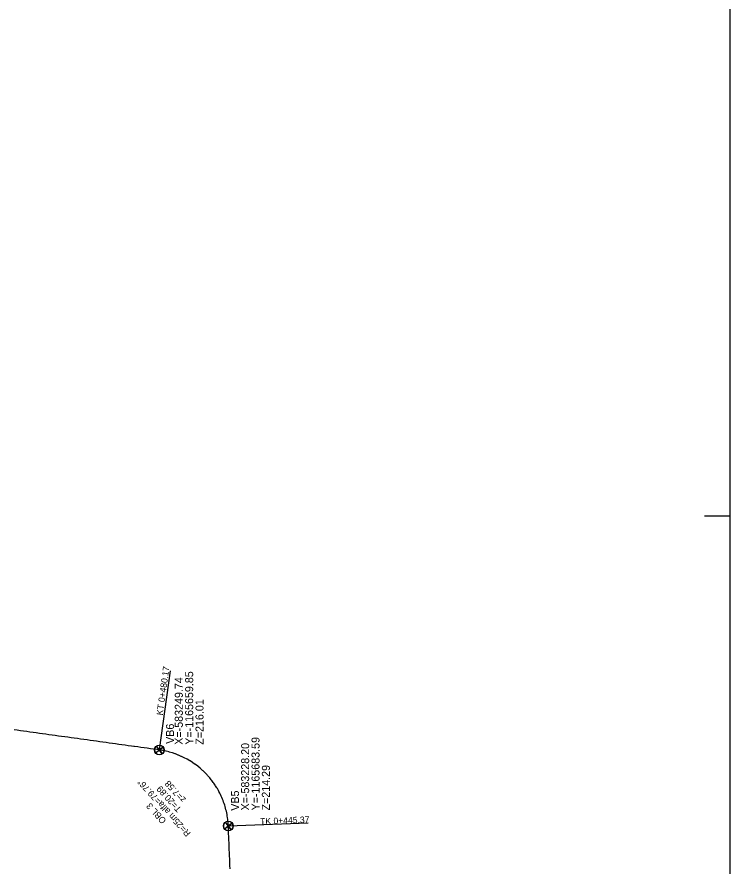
# Model space of a CAD drawing. Extents: x -583517 to -548566, y -1166112 to -1101582.
# Drawn here: x -583294.2 to -583071.5, y -1165696.4 to -1165430.8 of the extents above; entities that cross this region are included whole.
import ezdxf

# ---------------------------------------------------------------- set-up
doc = ezdxf.new("R2010")
doc.units = 0
for name, color, linetype in [('13', 7, 'Continuous'), ('59', 7, 'Continuous'), ('8', 7, 'Continuous'), ('Body pricny rez', 7, 'Continuous'), ('Popis pricneho profilu', 7, 'Continuous')]:
    doc.layers.add(name, color=color, linetype=linetype)

msp = doc.modelspace()

# ---------------------------------------------------------------- linework, layer by layer
at = {"layer": '13'}
for points in [[(-583249.74, -1165659.85), (-583246.31, -1165635.09)], [(-583228.2, -1165683.59), (-583203.22, -1165682.57)]]:
    msp.add_lwpolyline(points, dxfattribs=at)
at = {"layer": '8'}
for p, q in [((-583250.95, -1165660.74), (-583248.54, -1165658.95)), ((-583250.95, -1165660.74), (-583249.74, -1165659.85)), ((-583249.74, -1165659.85), (-583250.64, -1165658.64)), ((-583248.85, -1165661.05), (-583250.64, -1165658.65)), ((-583248.54, -1165658.95), (-583249.74, -1165659.85)), ((-583248.54, -1165658.95), (-583249.74, -1165659.85)), ((-583249.74, -1165659.85), (-583248.85, -1165661.05)), ((-583249.74, -1165659.85), (-583248.85, -1165661.05)), ((-583227.3, -1165684.79), (-583229.09, -1165682.39)), ((-583228.2, -1165683.59), (-583229.09, -1165682.39)), ((-583229.4, -1165684.48), (-583226.99, -1165682.69)), ((-583229.4, -1165684.48), (-583228.2, -1165683.59)), ((-583226.99, -1165682.69), (-583228.2, -1165683.59)), ((-583226.99, -1165682.69), (-583228.2, -1165683.59)), ((-583228.2, -1165683.59), (-583227.3, -1165684.79)), ((-583228.2, -1165683.59), (-583227.3, -1165684.79))]:
    msp.add_line(p, q, dxfattribs=at)
for centre in [(-583249.74, -1165659.85), (-583228.2, -1165683.59)]:
    msp.add_circle(centre, 1.5, dxfattribs=at)
for centre, start, end in [((-583249.74, -1165659.85), 126.6271, 216.6271), ((-583249.74, -1165659.85), 306.6271, 36.6271), ((-583249.74, -1165659.85), 306.6271, 36.6271), ((-583228.2, -1165683.59), 126.6271, 216.6271), ((-583228.2, -1165683.59), 306.6271, 36.6271), ((-583228.2, -1165683.59), 306.6271, 36.6271)]:
    msp.add_arc(centre, 1.5, start, end, dxfattribs=at)
at = {"layer": 'Body pricny rez'}
msp.add_lwpolyline([(-583227.65, -1165696.95), (-583227.69, -1165695.95), (-583227.73, -1165694.95), (-583227.77, -1165693.95), (-583227.81, -1165692.95), (-583227.85, -1165691.95), (-583227.9, -1165690.96), (-583227.91, -1165690.71), (-583227.94, -1165689.96), (-583227.98, -1165688.96), (-583228.02, -1165687.96), (-583228.06, -1165686.96), (-583228.1, -1165685.96), (-583228.14, -1165684.96), (-583228.18, -1165683.96), (-583228.2, -1165683.59), (-583228.23, -1165682.96), (-583228.26, -1165682.57), (-583228.32, -1165681.97), (-583228.36, -1165681.55), (-583228.44, -1165680.97), (-583228.51, -1165680.54), (-583228.61, -1165679.99), (-583228.7, -1165679.53), (-583228.81, -1165679.01), (-583228.93, -1165678.53), (-583229.06, -1165678.04), (-583229.2, -1165677.55), (-583229.34, -1165677.08), (-583229.5, -1165676.57), (-583229.66, -1165676.13), (-583229.85, -1165675.61), (-583230.02, -1165675.2), (-583230.24, -1165674.66), (-583230.41, -1165674.28), (-583230.67, -1165673.73), (-583230.84, -1165673.38), (-583231.13, -1165672.82), (-583231.31, -1165672.49), (-583231.63, -1165671.93), (-583231.81, -1165671.63), (-583232.17, -1165671.05), (-583232.35, -1165670.79), (-583232.74, -1165670.21), (-583232.92, -1165669.96), (-583233.35, -1165669.38), (-583233.52, -1165669.17), (-583233.99, -1165668.58), (-583234.15, -1165668.39), (-583234.66, -1165667.81), (-583234.82, -1165667.64), (-583235.37, -1165667.07), (-583235.51, -1165666.92), (-583236.1, -1165666.35), (-583236.23, -1165666.23), (-583236.86, -1165665.67), (-583236.98, -1165665.57), (-583237.65, -1165665.02), (-583237.75, -1165664.94), (-583238.47, -1165664.4), (-583238.55, -1165664.33), (-583239.3, -1165663.81), (-583239.38, -1165663.77), (-583240.17, -1165663.26), (-583240.22, -1165663.23), (-583241.05, -1165662.75), (-583241.09, -1165662.73), (-583241.96, -1165662.27), (-583241.97, -1165662.26), (-583242.87, -1165661.83), (-583242.88, -1165661.83), (-583243.79, -1165661.44), (-583243.82, -1165661.43), (-583244.73, -1165661.08), (-583244.78, -1165661.06), (-583245.67, -1165660.76), (-583245.75, -1165660.74), (-583246.63, -1165660.48), (-583246.73, -1165660.46), (-583247.6, -1165660.24), (-583247.73, -1165660.21), (-583248.58, -1165660.04), (-583248.73, -1165660.01), (-583249.57, -1165659.87), (-583249.74, -1165659.85), (-583250.56, -1165659.74), (-583251.55, -1165659.6), (-583252.54, -1165659.46), (-583253.53, -1165659.32), (-583254.52, -1165659.19), (-583255.51, -1165659.05), (-583256.5, -1165658.91), (-583257.49, -1165658.77), (-583257.74, -1165658.74), (-583258.48, -1165658.64), (-583259.47, -1165658.5), (-583260.46, -1165658.36), (-583261.46, -1165658.22), (-583262.45, -1165658.09), (-583263.44, -1165657.95), (-583264.43, -1165657.81), (-583265.42, -1165657.68), (-583266.41, -1165657.54), (-583267.4, -1165657.4), (-583268.39, -1165657.26), (-583269.38, -1165657.13), (-583270.37, -1165656.99), (-583271.36, -1165656.85), (-583272.35, -1165656.71), (-583273.34, -1165656.58), (-583274.33, -1165656.44), (-583275.32, -1165656.3), (-583276.31, -1165656.16), (-583277.3, -1165656.03), (-583278.29, -1165655.89), (-583279.28, -1165655.75), (-583280.28, -1165655.62), (-583281.27, -1165655.48), (-583282.26, -1165655.34), (-583283.25, -1165655.2), (-583284.24, -1165655.07), (-583285.23, -1165654.93), (-583286.22, -1165654.79), (-583287.21, -1165654.65), (-583288.2, -1165654.52), (-583289.19, -1165654.38), (-583290.18, -1165654.24), (-583291.17, -1165654.1), (-583292.16, -1165653.97), (-583293.15, -1165653.83), (-583294.14, -1165653.69), (-583295.13, -1165653.55)], dxfattribs=at)
at = {"layer": 'Popis pricneho profilu'}
msp.add_line((-583071.47, -1165586.82), (-583079.47, -1165586.82), dxfattribs=at)
msp.add_lwpolyline([(-583516.97, -1166111.82), (-583516.97, -1165166.82), (-583071.47, -1165166.82), (-583071.47, -1166111.82)], close=True, dxfattribs=at)

# ---------------------------------------------------------------- texts
at = {"layer": '13'}
for s, rotation, p in [('KT 0+480.17', 82.1049, (-583248.69, -1165649.11)), ('R=25m alfa=79.76%%d', 132.2246, (-583239.8, -1165685.78)), ('  T=20.89', 132.2246, (-583241.66, -1165679.26)), ('   z=7.58', 132.2246, (-583239.81, -1165676.84)), ('OBL 3', 132.2246, (-583247.44, -1165681.82)), ('TK 0+445.37', 2.3443, (-583218.21, -1165683.18))]:
    msp.add_text(s, height=2, rotation=rotation, dxfattribs=at).set_placement(p)
at = {"layer": '59'}
for s, p in [('X=-583249.74', (-583242.42, -1165658.21)), ('Y=-1165659.85', (-583239.18, -1165658.21)), ('Z=216.01', (-583235.95, -1165658.21)), ('VB6', (-583245.16, -1165657.94)), ('X=-583228.20', (-583221.69, -1165678.75)), ('Y=-1165683.59', (-583218.45, -1165678.75)), ('Z=214.29', (-583215.22, -1165678.75)), ('VB5', (-583224.86, -1165678.84))]:
    msp.add_text(s, height=2.5, rotation=90, dxfattribs=at).set_placement(p)

doc.saveas('drawing.dxf')
